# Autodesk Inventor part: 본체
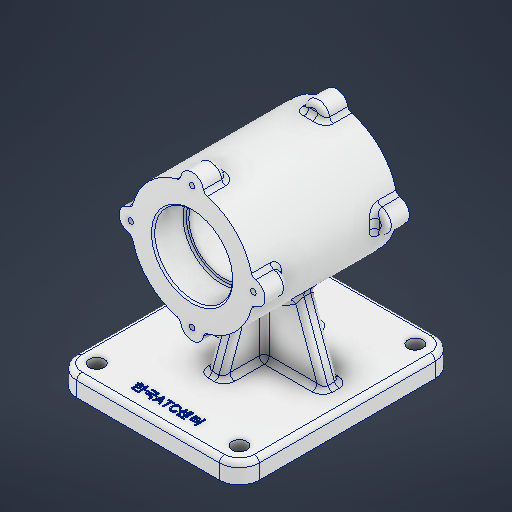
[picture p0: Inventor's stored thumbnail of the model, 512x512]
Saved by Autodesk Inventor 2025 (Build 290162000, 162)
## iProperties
Created: 2025-08
Part Number: 본체
Material: 알루미늄 6061
Document SubType Name: Modeling
Designer: infra17
Density: 2.7 g/cm^3
Appearance: 알루미늄 - 평지
Mass: 1222.68 g
Surface Area: 800.379 cm^2
Volume: 452.843 cm^3
Author: infra17
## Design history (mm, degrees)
sketch "스케치1"
  geometry: L1 (55, 65)-(-55, 65); L2 (-55, 65)-(-55, -65); L3 (-55, -65)-(55, -65); L4 (55, -65)-(55, 65); 1 further point
  constraints: 8 end point, 3 perpendicular, 1 horizontal
  dimensions: "d0" = 130 distance between parallel lines of L3 L1; "d1" = 65 distance from line of L3 point (0, 0) (= 0.5 x d0); "d3" = 110 distance between parallel lines of L2 L4; "d4" = 55 distance from line of point (0, 0) L4
extrude "돌출1" new body sketch "스케치1" distance "d5" = 12; taper "d6" = 0 deg
sketch "스케치2"
  geometry: 1 further point
sketch "스케치4"
  geometry: L1 (119, 38.5)-(105.5, 38.5); L2 (105.5, 38.5)-(105.5, 19.5); L3 (105.5, 19.5)-(103, 19.5); L4 (103, 19.5)-(103, -29.5); L5 (103, -29.5)-(105.5, -29.5); L6 (105.5, -29.5)-(105.5, -48.5); L7 (105.5, -48.5)-(119, -48.5); L8 (119, -48.5)-(119, 38.5); L9 (0, 65)-(12, 65) reference; L10 (82, 34.448)-(82, -42.135); L11 (0, 65)-(0, -65) reference; 4 further points
  constraints: 18 end point, 6 perpendicular, 3 midpoint, 2 point on line, 1 horizontal, 1 vertical
  dimensions: "d9" = 19 distance from line of point (104.25, 19.5) L1; "d10" = 87 distance from line of point (112.25, -48.5) L1; "d11" = 19 distance of L5.end L6.end; "d13" = 70 distance from line of point (119, -5) L9; "d14" = 82 distance between parallel lines of L11 L10; "d15" = 21 distance between parallel lines of L10 L4; "d16" = 23.5 distance between parallel lines of L10 L6; "d17" = 37 distance between parallel lines of L10 L8
revolve "회전1" sketch "스케치4" stored, may be unused: angle "d18" = 90 deg
sketch "스케치5"
  geometry: C1 r 7 at (0, 37); C2 r 7 at (-37, 0); C3 r 7 at (0, -37); C4 r 7 at (37, 0); 2 further points
  constraints: 4 centre point, 2 vertical alignment, 10 other
  dimensions: "d19" = 14 diameter of C1; "d22" = 360 deg dimension on point (0, 0) C1.centre (derived)
extrude "돌출2" join sketch "스케치5" distance "d24" = 14; taper "d25" = 0 deg
sketch "스케치6"
  geometry: C1 r 7 at (0, 37); C2 r 7 at (-37, 0); C3 r 7 at (0, -37); C4 r 7 at (37, 0); 4 further points
  constraints: 4 centre point, 1 vertical alignment, 11 other
  dimensions: "d26" = 14 diameter of C1; "d29" = 360 deg dimension on point (0, 0) C1.centre (derived)
extrude "돌출3" join sketch "스케치6" distance "d31" = 14; taper "d32" = 0 deg
chamfer "모따기1" distance "d33" = 1; stored, may be unused: second distance "d34" = 2, angle "d35" = 45 deg
sketch "스케치7"
  geometry: L1 (0, 37)-(0, 74); L2 (-55, -33)-(55, -33) reference; L3 (-55, -45)-(55, -45) reference; 7 further points
  constraints: 2 end point, 2 midpoint, 1 coincident, 1 vertical, 1 vertical alignment, 5 other
  dimensions: "d36" = 37 distance of L1.start L1.end; "d37" = 82 distance of point (0, -45) L1.start; "d40" = 360 deg dimension on L1.start point (0, 74) (derived)
hole "구멍1" sketch "스케치7" at (0, 74), (37, 37), (0, 0), (-37, 37) diameter "d42" = 3.242; stored, may be unused: countersink angle "d46" = 90 deg, drill point angle "d48" = 118 deg; dims "d43" = 8, "d44" = 8, "d45" = 4.4, "d47" = 10
sketch "스케치8"
  geometry: L1 (0, -37)-(0, 0); L2 (-55, -107)-(55, -107) reference; L3 (-55, -119)-(55, -119) reference; L4 (0, -37)-(-37, -37); L5 (0, -37)-(0, -74); L6 (0, -37)-(37, -37); 7 further points
  constraints: 8 end point, 6 coincident, 2 midpoint, 1 vertical, 1 vertical alignment, 15 other
  dimensions: "d49" = 82 distance of point (0, -119) L1.start; "d50" = 37 distance of L1.start L1.end; "d53" = 360 deg dimension on L1.start L1.end (derived)
hole "구멍2" sketch "스케치8" at (0, 0), (37, -37), (0, -74), (-37, -37) diameter "d55" = 3.242; stored, may be unused: countersink angle "d59" = 90 deg, drill point angle "d61" = 118 deg; dims "d56" = 8, "d57" = 4, "d58" = 2, "d60" = 10
sketch "스케치9"
  geometry: L1 (-4.685, -59.739)-(4.685, -59.739); L2 (4.685, -59.739)-(4.685, -46.261); L3 (4.685, -46.261)-(-4.685, -46.261); L4 (-4.685, -46.261)-(-4.685, -59.739); L5 (-55, -65)-(55, -65) reference; 7 further points
  constraints: 6 midpoint, 2 vertical alignment, 2 other
  dimensions: "d101" = 12 vertical distance of point (0, -65) point (4.685, -53)
sketch "스케치10"
  geometry: L1 (-55, 65)-(-55, -65) reference; L2 (0, 0)-(-16.743, 0); L3 (-16.743, 0)-(17.214, 0); C1 r 4.5 at (-43, 53); C2 r 4.5 at (43, 53); C3 r 4.5 at (-43, -53); C4 r 4.5 at (43, -53)
  constraints: 4 centre point, 4 end point, 2 symmetric about line, 1 horizontal, 1 horizontal alignment, 1 point on line, 2 other
  dimensions: "d62" = 9 diameter of C1; "d63" = 12 distance from line of L1 C1.centre; "d64" = 9 diameter of C2; "d65" = 86 distance of C2.centre C1.centre; "d66" = 53 distance from line of L2 C1.centre
extrude "돌출4" cut sketch "스케치10" distance "d67" = 14; taper "d68" = 0 deg
fillet "모깎기1" dims "d69" = 12
sketch "스케치11"
  geometry: L1 (12, 53)-(12, -53) reference; L2 (12, -35)-(49.407, -21.385); L3 (12, 25)-(54.435, 9.555); L4 (0, 65)-(12, 65) reference; L5 (12, 25)-(12, -35); L6 (54.435, 9.555)-(49.407, -21.385); 1 further point
  constraints: 8 end point, 2 point on line, 2 vertical alignment, 1 collinear
  dimensions: "d70" = 110 deg angle of L1 L2; "d71" = 110 deg angle of L1 L3; "d72" = 60 distance of L2.start L3.start; "d73" = 42.43456 horizontal distance of L3.start L3.end; "d74" = 37.40716 horizontal distance of L2.start L2.end; "d75" = 40 distance from line of L4 L3.start
extrude "돌출5" join sketch "스케치11" stored distance "d76" = 10; taper "d77" = 0 deg
node "작업 평면1"
sketch "스케치12"
  geometry: L1 (17.851, 55.55)-(2, 12); L2 (86, 12)-(0, 12) reference; L3 (68.002, 55.954)-(84, 12); L4 (-12, 0)-(-12, 12) reference; L5 (98, 12)-(98, 0) reference; L6 (-12, 12)-(0, 12) reference; L7 (86, 12)-(98, 12) reference; 1 further point
  constraints: 4 end point, 2 point on line
  dimensions: "d79" = 14 distance from line of L4 L1.end; "d80" = 14 distance from line of L5 L3.end; "d81" = 110 deg angle of L6 L1; "d82" = 110 deg angle of L7 L3; "d83" = 46.34494 distance of L1.start L1.end; "d84" = 46.77482 distance of L3.start L3.end
feature "리브1" dims "d85" = 1, "d86" = 10, "d87" = 0, "d88" = 0, "d89" = 1, "d90" = 1
feature "리브2" dims "d91" = 1, "d92" = 10, "d93" = 0, "d94" = 0, "d95" = 1, "d96" = 1
fillet "모깎기2" dims "d97" = 3
fillet "모깎기3" dims "d98" = 3
fillet "모깎기4" dims "d99" = 1
fillet "모깎기5" dims "d100" = 3
feature "엠보싱1" dims "d0" = 130, "d1" = 65 (= 0.5 x d0), "d3" = 110, "d4" = 55, "d15" = 21, "d102" = 0.5, "d103" = 0
node "솔리드1"
node "스케치 - 원형 패턴1" dims "d22" = 360 deg (derived)
node "스케치 - 원형 패턴2" dims "d29" = 360 deg (derived)
node "스케치 - 원형 패턴3" dims "d40" = 360 deg (derived)
node "스케치 - 원형 패턴4" dims "d53" = 360 deg (derived)
feature "A9D066F2-1C7D-4E18-AEED-F7BC21143FA4" dims "d42" = 3.242, "d43" = 8, "d44" = 8, "d45" = 4.4, "d46" = 90 deg, "d47" = 10, "d48" = 118 deg
